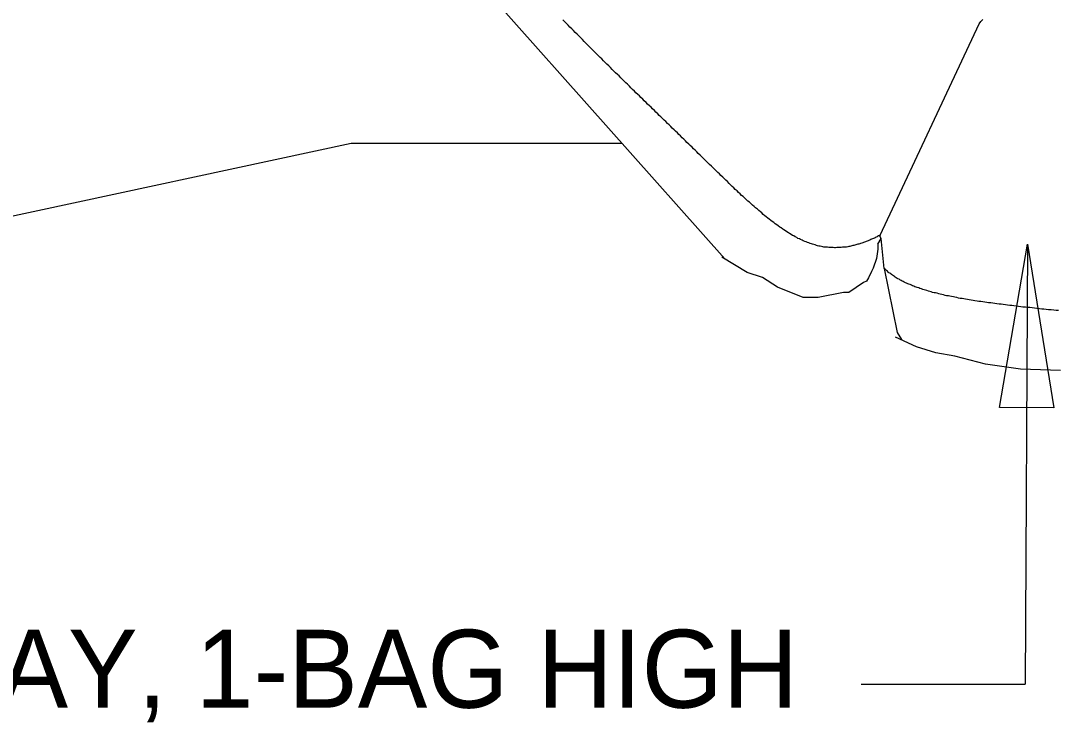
# Model space of a CAD drawing. Extents: x 6707406 to 6714471, y 1868570 to 1872341.
# Drawn here: x 6714208.7 to 6714288.5, y 1870045.9 to 1870099.9 of the extents above; entities that cross this region are included whole.
import ezdxf

# ---------------------------------------------------------------- set-up
doc = ezdxf.new("R2010")
doc.units = 0
doc.layers.add('Nongeo Data(60)', color=7, linetype='Continuous')

msp = doc.modelspace()

# ---------------------------------------------------------------- linework, layer by layer
at = {"layer": 'Nongeo Data(60)'}
for p, q in [((6714262.872, 1870081.591), (6714238.414, 1870109.104)), ((6714274.838, 1870083.429), (6714282.439, 1870099.688)), ((6714203.597, 1870083.957), (6714234.119, 1870090.502)), ((6714234.119, 1870090.502), (6714254.949, 1870090.502)), ((6714274.654, 1870082.74), (6714274.906, 1870083.153)), ((6714274.906, 1870083.153), (6714274.769, 1870083.383)), ((6714274.654, 1870082.349), (6714274.539, 1870081.614)), ((6714274.654, 1870082.74), (6714274.654, 1870082.349)), ((6714286.16, 1870082.74), (6714285.976, 1870048.888)), ((6714264.595, 1870080.558), (6714262.643, 1870081.729)), ((6714274.539, 1870081.614), (6714274.286, 1870080.879)), ((6714274.286, 1870080.879), (6714274.172, 1870080.627)), ((6714275.136, 1870080.856), (6714276.147, 1870075.942)), ((6714275.136, 1870080.856), (6714275.136, 1870080.856)), ((6714275.136, 1870080.856), (6714275.136, 1870080.856)), ((6714275.136, 1870080.856), (6714275.136, 1870080.856)), ((6714275.136, 1870080.856), (6714275.136, 1870080.856)), ((6714265.766, 1870080.167), (6714264.595, 1870080.558)), ((6714266.937, 1870079.41), (6714265.766, 1870080.167)), ((6714273.781, 1870079.892), (6714273.551, 1870079.777)), ((6714273.919, 1870080.144), (6714273.781, 1870079.892)), ((6714274.172, 1870080.627), (6714273.919, 1870080.144)), ((6714268.889, 1870078.629), (6714266.937, 1870079.41)), ((6714273.551, 1870079.777), (6714272.403, 1870079.019)), ((6714270.061, 1870078.629), (6714268.889, 1870078.629)), ((6714272.013, 1870079.019), (6714270.061, 1870078.629)), ((6714272.403, 1870079.019), (6714272.013, 1870079.019)), ((6714276.147, 1870075.942), (6714276.468, 1870075.391)), ((6714276.147, 1870075.942), (6714276.147, 1870075.942)), ((6714276.147, 1870075.942), (6714276.147, 1870075.942)), ((6714276.147, 1870075.942), (6714276.147, 1870075.942)), ((6714276.147, 1870075.942), (6714276.147, 1870075.942)), ((6714276.147, 1870075.942), (6714276.147, 1870075.942)), ((6714276.147, 1870075.942), (6714276.147, 1870075.942)), ((6714276.147, 1870075.942), (6714276.147, 1870075.942)), ((6714276.147, 1870075.942), (6714276.147, 1870075.942)), ((6714276.147, 1870075.942), (6714276.147, 1870075.942)), ((6714276.147, 1870075.942), (6714276.147, 1870075.942)), ((6714276.147, 1870075.942), (6714276.147, 1870075.942)), ((6714276.147, 1870075.942), (6714276.147, 1870075.942)), ((6714276.147, 1870075.942), (6714276.147, 1870075.942)), ((6714276.147, 1870075.942), (6714276.147, 1870075.942)), ((6714276.147, 1870075.942), (6714276.147, 1870075.942)), ((6714276.147, 1870075.942), (6714276.147, 1870075.942)), ((6714276.147, 1870075.942), (6714276.147, 1870075.942)), ((6714277.616, 1870074.839), (6714276.009, 1870075.574)), ((6714279.109, 1870074.357), (6714277.616, 1870074.839)), ((6714280.579, 1870074.104), (6714279.109, 1870074.357)), ((6714282.922, 1870073.484), (6714280.579, 1870074.104)), ((6714285.632, 1870073.117), (6714282.922, 1870073.484)), ((6714288.709, 1870073.002), (6714285.632, 1870073.117)), ((6714273.368, 1870048.888), (6714285.976, 1870048.888))]:
    msp.add_line(p, q, dxfattribs=at)
for points in [[(6714254.467, 1870095.922), (6714254.329, 1870096.037), (6714254.191, 1870096.175), (6714254.076, 1870096.312), (6714253.939, 1870096.45), (6714253.801, 1870096.565), (6714253.663, 1870096.703), (6714253.525, 1870096.841), (6714253.41, 1870096.978), (6714253.273, 1870097.093), (6714253.135, 1870097.231), (6714252.997, 1870097.369), (6714252.859, 1870097.507), (6714252.721, 1870097.644), (6714252.584, 1870097.782), (6714252.446, 1870097.92), (6714252.308, 1870098.058), (6714252.17, 1870098.196), (6714252.055, 1870098.333), (6714251.918, 1870098.471), (6714251.78, 1870098.609), (6714251.642, 1870098.747), (6714251.504, 1870098.885), (6714251.366, 1870099.022), (6714251.229, 1870099.16), (6714251.091, 1870099.298), (6714250.953, 1870099.436), (6714250.815, 1870099.574), (6714250.677, 1870099.711), (6714250.54, 1870099.849), (6714250.402, 1870099.987)], [(6714282.439, 1870099.688), (6714282.577, 1870099.872), (6714282.738, 1870100.01)], [(6714262.574, 1870087.999), (6714262.459, 1870088.137), (6714262.321, 1870088.251), (6714262.206, 1870088.366), (6714262.092, 1870088.481), (6714261.954, 1870088.619), (6714261.839, 1870088.734), (6714261.701, 1870088.849), (6714261.586, 1870088.963), (6714261.471, 1870089.101), (6714261.334, 1870089.216), (6714261.219, 1870089.331), (6714261.081, 1870089.469), (6714260.966, 1870089.583), (6714260.828, 1870089.698), (6714260.714, 1870089.836), (6714260.599, 1870089.951), (6714260.461, 1870090.066), (6714260.346, 1870090.204), (6714260.208, 1870090.318), (6714260.093, 1870090.433), (6714259.956, 1870090.548), (6714259.841, 1870090.686), (6714259.726, 1870090.801), (6714259.588, 1870090.915), (6714259.473, 1870091.053), (6714259.336, 1870091.168), (6714259.221, 1870091.283), (6714259.083, 1870091.421), (6714258.968, 1870091.536), (6714258.83, 1870091.65), (6714258.716, 1870091.788), (6714258.578, 1870091.903), (6714258.463, 1870092.018), (6714258.325, 1870092.156), (6714258.21, 1870092.27), (6714258.072, 1870092.385), (6714257.958, 1870092.523), (6714257.82, 1870092.638), (6714257.705, 1870092.753), (6714257.567, 1870092.891), (6714257.452, 1870093.005), (6714257.315, 1870093.143), (6714257.2, 1870093.258), (6714257.062, 1870093.373), (6714256.924, 1870093.511), (6714256.809, 1870093.625), (6714256.672, 1870093.763), (6714256.557, 1870093.878), (6714256.419, 1870094.016), (6714256.304, 1870094.131), (6714256.166, 1870094.245), (6714256.029, 1870094.383), (6714255.914, 1870094.498), (6714255.776, 1870094.636), (6714255.638, 1870094.751), (6714255.523, 1870094.889), (6714255.385, 1870095.026), (6714255.248, 1870095.141), (6714255.133, 1870095.279), (6714254.995, 1870095.394), (6714254.857, 1870095.532), (6714254.742, 1870095.669), (6714254.605, 1870095.784), (6714254.467, 1870095.922)], [(6714269.831, 1870082.671), (6714269.716, 1870082.694), (6714269.624, 1870082.717), (6714269.532, 1870082.763), (6714269.441, 1870082.786), (6714269.326, 1870082.831), (6714269.234, 1870082.854), (6714269.119, 1870082.9), (6714269.027, 1870082.946), (6714268.912, 1870082.992), (6714268.821, 1870083.038), (6714268.706, 1870083.084), (6714268.614, 1870083.13), (6714268.499, 1870083.176), (6714268.407, 1870083.245), (6714268.292, 1870083.291), (6714268.177, 1870083.36), (6714268.086, 1870083.406), (6714267.971, 1870083.474), (6714267.856, 1870083.543), (6714267.764, 1870083.612), (6714267.649, 1870083.681), (6714267.534, 1870083.75), (6714267.42, 1870083.819), (6714267.328, 1870083.888), (6714267.213, 1870083.98), (6714267.098, 1870084.049), (6714266.983, 1870084.141), (6714266.868, 1870084.209), (6714266.754, 1870084.301), (6714266.639, 1870084.393), (6714266.524, 1870084.462), (6714266.409, 1870084.554), (6714266.294, 1870084.646), (6714266.179, 1870084.738), (6714266.065, 1870084.829), (6714265.95, 1870084.921), (6714265.835, 1870085.013), (6714265.72, 1870085.128), (6714265.605, 1870085.22), (6714265.49, 1870085.312), (6714265.376, 1870085.427), (6714265.238, 1870085.518), (6714265.123, 1870085.633), (6714265.008, 1870085.725), (6714264.893, 1870085.84), (6714264.779, 1870085.955), (6714264.641, 1870086.047), (6714264.526, 1870086.162), (6714264.411, 1870086.276), (6714264.296, 1870086.391), (6714264.158, 1870086.483), (6714264.044, 1870086.598), (6714263.929, 1870086.713), (6714263.814, 1870086.828), (6714263.676, 1870086.942), (6714263.561, 1870087.057), (6714263.446, 1870087.172), (6714263.309, 1870087.287), (6714263.194, 1870087.402), (6714263.079, 1870087.539), (6714262.941, 1870087.654), (6714262.826, 1870087.769), (6714262.712, 1870087.884), (6714262.574, 1870087.999)], [(6714274.838, 1870083.429), (6714274.838, 1870083.406), (6714274.769, 1870083.383), (6714274.7, 1870083.36), (6714274.631, 1870083.314), (6714274.585, 1870083.291), (6714274.516, 1870083.268), (6714274.447, 1870083.222), (6714274.378, 1870083.199), (6714274.309, 1870083.176), (6714274.24, 1870083.13), (6714274.172, 1870083.107), (6714274.103, 1870083.084), (6714274.034, 1870083.038), (6714273.965, 1870083.015), (6714273.896, 1870082.992), (6714273.827, 1870082.969), (6714273.758, 1870082.946), (6714273.689, 1870082.9), (6714273.62, 1870082.877), (6714273.551, 1870082.854), (6714273.483, 1870082.831), (6714273.414, 1870082.808), (6714273.322, 1870082.786), (6714273.253, 1870082.763), (6714273.184, 1870082.74), (6714273.115, 1870082.717), (6714273.023, 1870082.694), (6714272.954, 1870082.671), (6714272.885, 1870082.648), (6714272.794, 1870082.625), (6714272.725, 1870082.625), (6714272.656, 1870082.602), (6714272.564, 1870082.579), (6714272.495, 1870082.556), (6714272.403, 1870082.556), (6714272.334, 1870082.533), (6714272.242, 1870082.51), (6714272.151, 1870082.51), (6714272.082, 1870082.487), (6714271.99, 1870082.487), (6714271.921, 1870082.487), (6714271.829, 1870082.464), (6714271.737, 1870082.464), (6714271.645, 1870082.464), (6714271.576, 1870082.464), (6714271.485, 1870082.464), (6714271.393, 1870082.441), (6714271.301, 1870082.441), (6714271.209, 1870082.464), (6714271.14, 1870082.464), (6714271.048, 1870082.464), (6714270.956, 1870082.464), (6714270.864, 1870082.464), (6714270.773, 1870082.487), (6714270.681, 1870082.487), (6714270.589, 1870082.51), (6714270.497, 1870082.51), (6714270.405, 1870082.533), (6714270.313, 1870082.556), (6714270.198, 1870082.579), (6714270.107, 1870082.579), (6714270.015, 1870082.602), (6714269.923, 1870082.625), (6714269.831, 1870082.671)], [(6714277.892, 1870079.318), (6714277.8, 1870079.364), (6714277.685, 1870079.387), (6714277.593, 1870079.433), (6714277.502, 1870079.455), (6714277.41, 1870079.501), (6714277.318, 1870079.524), (6714277.226, 1870079.57), (6714277.134, 1870079.616), (6714277.042, 1870079.639), (6714276.95, 1870079.685), (6714276.859, 1870079.731), (6714276.767, 1870079.754), (6714276.675, 1870079.8), (6714276.606, 1870079.846), (6714276.514, 1870079.892), (6714276.445, 1870079.938), (6714276.353, 1870079.984), (6714276.284, 1870080.03), (6714276.193, 1870080.053), (6714276.124, 1870080.099), (6714276.055, 1870080.144), (6714275.986, 1870080.19), (6714275.917, 1870080.236), (6714275.848, 1870080.282), (6714275.779, 1870080.351), (6714275.71, 1870080.397), (6714275.641, 1870080.443), (6714275.572, 1870080.489), (6714275.504, 1870080.535), (6714275.435, 1870080.581), (6714275.389, 1870080.65), (6714275.32, 1870080.696), (6714275.251, 1870080.742), (6714275.205, 1870080.81), (6714275.136, 1870080.856), (6714274.906, 1870083.153)], [(6714287.078, 1870077.756), (6714286.895, 1870077.779), (6714286.711, 1870077.802), (6714286.527, 1870077.825), (6714286.343, 1870077.848), (6714286.183, 1870077.848), (6714285.999, 1870077.871), (6714285.815, 1870077.894), (6714285.655, 1870077.917), (6714285.471, 1870077.94), (6714285.31, 1870077.963), (6714285.126, 1870077.986), (6714284.966, 1870078.009), (6714284.805, 1870078.009), (6714284.621, 1870078.032), (6714284.46, 1870078.055), (6714284.3, 1870078.078), (6714284.139, 1870078.1), (6714283.978, 1870078.123), (6714283.817, 1870078.146), (6714283.656, 1870078.169), (6714283.496, 1870078.192), (6714283.335, 1870078.215), (6714283.174, 1870078.215), (6714283.036, 1870078.238), (6714282.876, 1870078.261), (6714282.715, 1870078.284), (6714282.577, 1870078.307), (6714282.416, 1870078.33), (6714282.279, 1870078.353), (6714282.118, 1870078.376), (6714281.98, 1870078.399), (6714281.842, 1870078.422), (6714281.681, 1870078.445), (6714281.544, 1870078.468), (6714281.406, 1870078.491), (6714281.268, 1870078.514), (6714281.13, 1870078.537), (6714280.992, 1870078.56), (6714280.855, 1870078.583), (6714280.717, 1870078.629), (6714280.579, 1870078.652), (6714280.464, 1870078.675), (6714280.326, 1870078.698), (6714280.189, 1870078.721), (6714280.074, 1870078.744), (6714279.936, 1870078.766), (6714279.821, 1870078.789), (6714279.706, 1870078.835), (6714279.569, 1870078.858), (6714279.454, 1870078.881), (6714279.339, 1870078.904), (6714279.224, 1870078.95), (6714279.086, 1870078.973), (6714278.971, 1870078.996), (6714278.857, 1870079.019), (6714278.742, 1870079.065), (6714278.65, 1870079.088), (6714278.535, 1870079.111), (6714278.42, 1870079.157), (6714278.305, 1870079.18), (6714278.214, 1870079.226), (6714278.099, 1870079.249), (6714278.007, 1870079.295), (6714277.892, 1870079.318)], [(6714288.548, 1870077.618), (6714288.364, 1870077.618), (6714288.181, 1870077.641), (6714287.997, 1870077.664), (6714287.79, 1870077.687), (6714287.607, 1870077.71), (6714287.423, 1870077.733), (6714287.262, 1870077.733), (6714287.078, 1870077.756)]]:
    msp.add_lwpolyline(points, dxfattribs=at)
msp.add_lwpolyline([(6714284.001, 1870070.154), (6714286.16, 1870082.74), (6714288.204, 1870070.131)], close=True, dxfattribs=at)

# ---------------------------------------------------------------- texts
msp.add_text('SPILLWAY, 1-BAG HIGH', height=6, dxfattribs=at).set_placement((6714177.549, 1870047.062))

doc.saveas('drawing.dxf')
